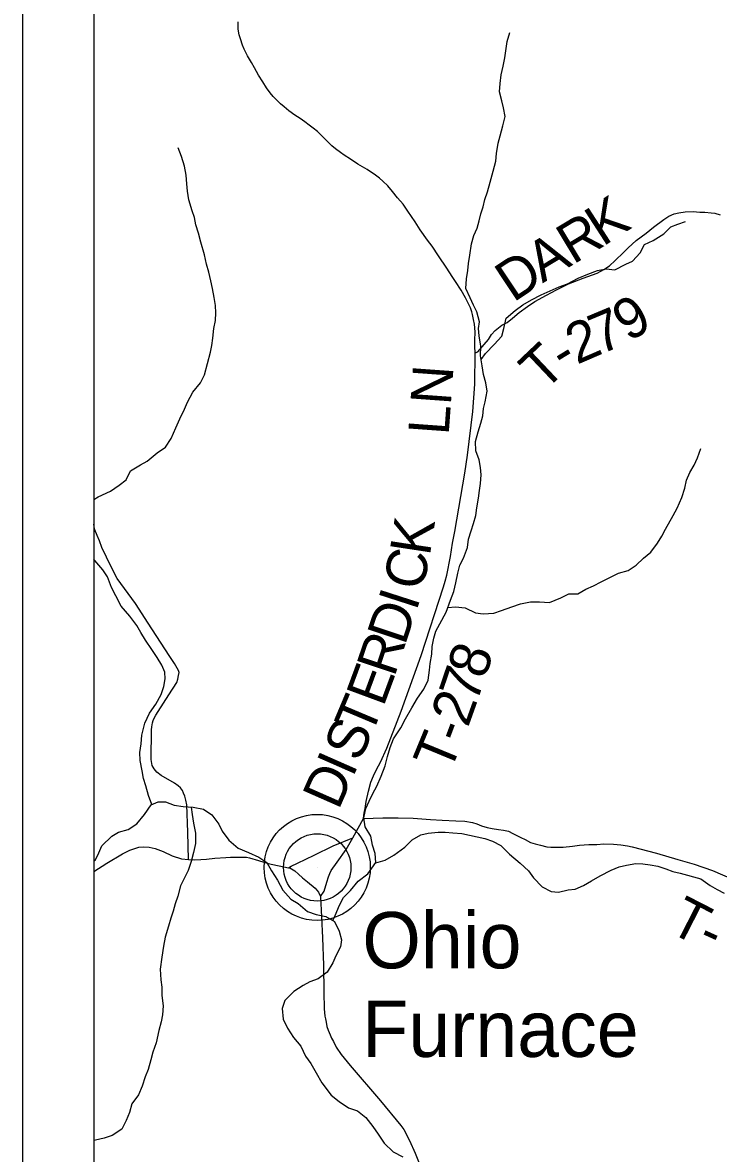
# Model space of a CAD drawing. Extents: x 0 to 34, y 0 to 22.
# Drawn here: x 2 to 2.975, y 14.962 to 16.547 of the extents above; entities that cross this region are included whole.
import ezdxf

# ---------------------------------------------------------------- set-up
doc = ezdxf.new("R2010")
doc.units = 0
for name, color, linetype in [('GM_X_County_Road', 7, 'Continuous'), ('GM_X_County_Text', 7, 'Continuous'), ('GM_X_Minor_River', 7, 'Continuous'), ('GM_X_Township_Road', 7, 'Continuous'), ('GM_X_Township_Road_Text', 7, 'Continuous'), ('GM_X_Unincorporated', 7, 'Continuous'), ('GM_X_Unincorporated_Location', 7, 'Continuous'), ('GM_X_Unincorporated_Text', 7, 'Continuous'), ('SH_Cut_Line', 7, 'Continuous'), ('SH_Data', 7, 'Continuous')]:
    doc.layers.add(name, color=color, linetype=linetype)

msp = doc.modelspace()

# ---------------------------------------------------------------- linework, layer by layer
at = {"layer": 'GM_X_County_Road'}
msp.add_lwpolyline([(2.1, 15.3571), (2.1182, 15.3686), (2.14, 15.3816), (2.1501, 15.387), (2.1572, 15.3894), (2.1627, 15.3911), (2.1701, 15.3915), (2.1772, 15.3913), (2.1859, 15.389), (2.1972, 15.3848), (2.2097, 15.3791), (2.2225, 15.3749), (2.2326, 15.3739), (2.2411, 15.3731), (2.2498, 15.3737), (2.2577, 15.3745), (2.2696, 15.3757), (2.2847, 15.3767), (2.2914, 15.3771), (2.2979, 15.3769), (2.3066, 15.3773), (2.3136, 15.3773), (2.3181, 15.3761), (2.3308, 15.3725), (2.3444, 15.3682), (2.3725, 15.3622), (2.3745, 15.3619), (2.3814, 15.3577), (2.3868, 15.3531), (2.3925, 15.3482), (2.3992, 15.3425), (2.4099, 15.3334), (2.4145, 15.3278), (2.4177, 15.3219), (2.4204, 15.2641), (2.4218, 15.2257), (2.4224, 15.1879), (2.4228, 15.1645), (2.4236, 15.1542), (2.4244, 15.1503), (2.4254, 15.1459), (2.4266, 15.1398), (2.4283, 15.1345), (2.4309, 15.1281), (2.4329, 15.1232), (2.4357, 15.1184), (2.4396, 15.1107), (2.4463, 15.1004), (2.459, 15.0848), (2.5018, 15.0353), (2.5299, 15.0009), (2.5342, 14.9951), (2.5425, 14.9799), (2.5502, 14.9621), (2.5617, 14.9332)], dxfattribs=at)
at = {"layer": 'GM_X_Minor_River'}
for points in [[(2.6761, 16.498), (2.6773, 16.5075), (2.6793, 16.5207), (2.6828, 16.5332)], [(2.4347, 15.2883), (2.438, 15.2952), (2.4442, 15.3096), (2.4499, 15.3205), (2.4594, 15.3303), (2.4705, 15.3436), (2.4838, 15.3537), (2.4952, 15.3696), (2.4942, 15.3821), (2.4905, 15.3939), (2.4879, 15.4064), (2.48, 15.4197), (2.4782, 15.4323), (2.4813, 15.4451), (2.4859, 15.4554), (2.4909, 15.4663), (2.4963, 15.4765), (2.5024, 15.4905), (2.5082, 15.5049), (2.5113, 15.5182), (2.5151, 15.5307), (2.5197, 15.5428), (2.53, 15.5583), (2.5369, 15.5711), (2.5457, 15.5866), (2.5537, 15.6002), (2.5625, 15.6127), (2.5686, 15.6252), (2.5702, 15.6392), (2.5711, 15.6487), (2.5734, 15.6619), (2.5742, 15.6725), (2.5762, 15.6843), (2.5793, 15.6941), (2.585, 15.7043), (2.5938, 15.7206), (2.5996, 15.7376), (2.6042, 15.7497), (2.6073, 15.7618), (2.61, 15.7751), (2.6127, 15.7865), (2.6181, 15.7963), (2.6235, 15.8114), (2.6251, 15.8228), (2.6285, 15.8345), (2.632, 15.8448), (2.6351, 15.8561), (2.6367, 15.8667), (2.639, 15.8804), (2.6402, 15.891), (2.6418, 15.9012), (2.6426, 15.913), (2.6416, 15.9236), (2.6397, 15.9342), (2.6353, 15.9468), (2.6346, 15.9597), (2.6385, 15.9733), (2.6423, 15.9858), (2.645, 15.996), (2.6462, 16.0062), (2.6482, 16.0157), (2.6513, 16.0305), (2.6495, 16.0419), (2.6458, 16.0537), (2.644, 16.0658), (2.6418, 16.0802), (2.6422, 16.0935), (2.6401, 16.1079), (2.639, 16.1182), (2.6402, 16.1276), (2.6365, 16.1417), (2.632, 16.1512), (2.6271, 16.1615), (2.6212, 16.1744), (2.622, 16.1881), (2.624, 16.1994), (2.6252, 16.2093), (2.6268, 16.221), (2.6291, 16.2369), (2.6326, 16.2487), (2.6372, 16.2589), (2.6399, 16.2691), (2.6422, 16.279), (2.6457, 16.2888), (2.648, 16.299), (2.6515, 16.31), (2.6554, 16.3233), (2.6596, 16.3388), (2.6631, 16.3528), (2.6643, 16.3638), (2.6667, 16.3782), (2.6694, 16.3884), (2.6733, 16.4024), (2.6764, 16.4153), (2.6742, 16.4278), (2.6716, 16.4377), (2.6683, 16.4499), (2.6695, 16.4616), (2.6707, 16.4741), (2.6734, 16.4862), (2.6761, 16.498)], [(2.1, 15.8784), (2.1058, 15.8821), (2.1233, 15.8903), (2.1351, 15.8986), (2.1453, 15.9061), (2.1511, 15.9186), (2.1651, 15.9272), (2.1746, 15.9321), (2.1887, 15.9441), (2.2004, 15.9517), (2.2081, 15.9641), (2.2146, 15.9789), (2.2203, 15.9917), (2.2269, 16.0054), (2.2311, 16.0152), (2.2387, 16.0288), (2.2494, 16.042), (2.2551, 16.0534), (2.2633, 16.0852), (2.2652, 16.0946), (2.2668, 16.1049), (2.268, 16.1181), (2.2704, 16.1295), (2.2708, 16.1401), (2.2705, 16.1504), (2.2687, 16.1617), (2.2661, 16.1743), (2.2639, 16.1853), (2.2609, 16.1971), (2.2576, 16.2085), (2.255, 16.2214), (2.2499, 16.2392), (2.2465, 16.2518), (2.2428, 16.2636), (2.241, 16.2738), (2.2376, 16.2833), (2.2328, 16.2985), (2.231, 16.311), (2.2303, 16.3209), (2.2293, 16.3334), (2.2271, 16.346), (2.2226, 16.3593), (2.2181, 16.3718)], [(2.6426, 16.0748), (2.649, 16.0832), (2.6608, 16.096), (2.6718, 16.1074), (2.6745, 16.1183), (2.678, 16.1327), (2.6906, 16.1437), (2.7012, 16.1516), (2.7133, 16.1583), (2.727, 16.1654), (2.752, 16.1767), (2.7638, 16.1811), (2.7786, 16.189), (2.7922, 16.1946), (2.8059, 16.1998), (2.818, 16.202), (2.8301, 16.2005), (2.8453, 16.2083), (2.8547, 16.2128), (2.8654, 16.2245), (2.8715, 16.2359), (2.884, 16.2415), (2.8988, 16.2509), (2.9087, 16.2607), (2.9182, 16.2644), (2.9292, 16.2681)], [(2.596, 15.727), (2.6067, 15.7281), (2.6203, 15.7265), (2.635, 15.7196), (2.6456, 15.7184), (2.6607, 15.7194), (2.671, 15.7231), (2.6857, 15.728), (2.6979, 15.7321), (2.7119, 15.735), (2.7244, 15.735), (2.7387, 15.7341), (2.7543, 15.7405), (2.7656, 15.7461), (2.7781, 15.7464), (2.7895, 15.7528), (2.8001, 15.7573), (2.8108, 15.7629), (2.8221, 15.7689), (2.8354, 15.7753), (2.849, 15.779), (2.8601, 15.7865), (2.8703, 15.7963), (2.8806, 15.8046), (2.8901, 15.8174), (2.8962, 15.8272), (2.9012, 15.8371), (2.9119, 15.856), (2.9176, 15.8662), (2.9242, 15.8813), (2.928, 15.8942), (2.9307, 15.9055), (2.9354, 15.9165), (2.9411, 15.9267), (2.9461, 15.9369), (2.9507, 15.9502)], [(2.1811, 15.4507), (2.1763, 15.4637), (2.1729, 15.477), (2.1696, 15.4876), (2.1674, 15.4979), (2.1648, 15.5127), (2.1641, 15.5237), (2.1661, 15.5362), (2.1673, 15.5479), (2.1712, 15.565), (2.1777, 15.579), (2.1869, 15.5918), (2.1941, 15.605), (2.198, 15.6164), (2.1996, 15.627), (2.1993, 15.6365), (2.1952, 15.6464), (2.1888, 15.657), (2.1813, 15.6681), (2.1723, 15.6814), (2.1659, 15.6921), (2.1603, 15.7019), (2.1502, 15.7149), (2.1382, 15.729), (2.1307, 15.7435), (2.1244, 15.7553), (2.1188, 15.7701), (2.1124, 15.78), (2.1011, 15.793), (2.1, 15.7948)], [(2.1, 15.3719), (2.102, 15.3735), (2.1069, 15.3833), (2.1108, 15.3931), (2.1249, 15.4067), (2.1343, 15.4119), (2.148, 15.416), (2.1601, 15.4239), (2.1708, 15.4371), (2.1803, 15.4504), (2.1898, 15.4545), (2.2004, 15.4548), (2.2125, 15.4502), (2.2249, 15.4482), (2.2389, 15.447), (2.2537, 15.4442), (2.2653, 15.4362), (2.2751, 15.4232), (2.2799, 15.4137), (2.2889, 15.4008)], [(2.2361, 15.4472), (2.2377, 15.4367), (2.2396, 15.4246), (2.2421, 15.4109), (2.2424, 15.3961), (2.2397, 15.3836), (2.2362, 15.3708), (2.232, 15.3583), (2.227, 15.3481), (2.2212, 15.3371), (2.2174, 15.3223), (2.2139, 15.3117), (2.2112, 15.3015), (2.2077, 15.2917), (2.2046, 15.2803), (2.2, 15.2651), (2.1976, 15.2523), (2.1953, 15.2367), (2.1929, 15.2201), (2.1936, 15.2053), (2.195, 15.195), (2.1953, 15.1833), (2.1971, 15.1684), (2.1959, 15.1559), (2.194, 15.1461), (2.1909, 15.134), (2.187, 15.1169), (2.1827, 15.1037), (2.1797, 15.0931), (2.1758, 15.0794), (2.1716, 15.0692), (2.1677, 15.056), (2.1623, 15.0439), (2.1532, 15.0314), (2.1497, 15.0189), (2.1451, 15.0079), (2.139, 14.9958), (2.1253, 14.9868), (2.1143, 14.9831), (2.1022, 14.9801), (2.1, 14.98)], [(2.4949, 15.3691), (2.5081, 15.3729), (2.5202, 15.3797), (2.5358, 15.391), (2.5461, 15.4015), (2.5582, 15.4083), (2.5685, 15.4109), (2.5825, 15.4119), (2.5923, 15.4119), (2.6029, 15.411), (2.6157, 15.4102), (2.6369, 15.4055), (2.6478, 15.4032), (2.6584, 15.3997), (2.6701, 15.3936), (2.6825, 15.3813), (2.6975, 15.3687), (2.7092, 15.358), (2.7159, 15.3481), (2.7283, 15.3356), (2.7408, 15.3287), (2.751, 15.3282), (2.7646, 15.3312), (2.7744, 15.3322), (2.7862, 15.3375), (2.7972, 15.3439), (2.8094, 15.351), (2.8249, 15.3589), (2.8363, 15.3633), (2.8465, 15.3659), (2.8594, 15.3681), (2.8692, 15.3677), (2.8798, 15.3665), (2.8904, 15.3645), (2.9017, 15.3607), (2.9115, 15.3568), (2.9217, 15.3545), (2.9504, 15.3467), (2.9636, 15.3375), (2.9737, 15.3318), (2.9835, 15.3268)], [(2.2889, 15.4008), (2.3021, 15.3897), (2.3168, 15.3835), (2.3311, 15.377), (2.3424, 15.3694), (2.3488, 15.3579), (2.3574, 15.3446), (2.3649, 15.3309), (2.3758, 15.318), (2.386, 15.3122), (2.3991, 15.3007), (2.4116, 15.2965), (2.4248, 15.2938), (2.4372, 15.2869), (2.4436, 15.2735), (2.4469, 15.2614), (2.4457, 15.2515), (2.4392, 15.2387), (2.4346, 15.2288), (2.427, 15.216), (2.4144, 15.2066), (2.4027, 15.2021), (2.3932, 15.1972), (2.3803, 15.1886), (2.3674, 15.1762), (2.3639, 15.1648), (2.3653, 15.15), (2.3713, 15.1371), (2.3799, 15.1241), (2.39, 15.1123), (2.3967, 15.0982), (2.4039, 15.0876), (2.4114, 15.0746), (2.4192, 15.0605), (2.4323, 15.0434), (2.4436, 15.0346), (2.4568, 15.0258), (2.4693, 15.0215), (2.4813, 15.012), (2.4907, 14.9994), (2.4982, 14.9888), (2.5068, 14.9762), (2.5192, 14.964), (2.5328, 14.9571)]]:
    msp.add_lwpolyline(points, dxfattribs=at)
at = {"layer": 'GM_X_Township_Road'}
for points in [[(2.3107, 16.5099), (2.3081, 16.5157), (2.3053, 16.5245), (2.3034, 16.53), (2.302, 16.5378), (2.3019, 16.5481)], [(2.4177, 15.3219), (2.4228, 15.3296), (2.4266, 15.3421), (2.4287, 15.3496), (2.4307, 15.3543), (2.4327, 15.3583), (2.441, 15.3702), (2.4535, 15.388), (2.463, 15.4044), (2.4776, 15.4315), (2.4784, 15.4359), (2.4793, 15.4409), (2.4801, 15.4453), (2.4816, 15.4549), (2.4849, 15.4698), (2.4883, 15.482), (2.492, 15.4912), (2.4962, 15.4998), (2.5017, 15.5104), (2.5105, 15.5297), (2.5304, 15.5816), (2.5584, 15.6597), (2.59, 15.7562), (2.5925, 15.7642), (2.5944, 15.7724), (2.5997, 15.7985), (2.6026, 15.8172), (2.6057, 15.8339), (2.62, 15.9154), (2.6237, 15.9407), (2.6309, 16.0021), (2.6338, 16.0404), (2.6343, 16.084), (2.6338, 16.093), (2.634, 16.1015), (2.6341, 16.1137), (2.6334, 16.1244), (2.6322, 16.1309), (2.6305, 16.1377), (2.6296, 16.1415), (2.6277, 16.1472), (2.6256, 16.152), (2.6208, 16.1611), (2.6149, 16.172), (2.6069, 16.184), (2.6022, 16.1914), (2.5947, 16.2027), (2.5827, 16.2204), (2.574, 16.2339), (2.5677, 16.2423), (2.5574, 16.2565), (2.55, 16.268), (2.5401, 16.2826), (2.5332, 16.2925), (2.5256, 16.3017), (2.5184, 16.3106), (2.5117, 16.3182), (2.5048, 16.3249), (2.5001, 16.3291), (2.4944, 16.3335), (2.4829, 16.3411), (2.47, 16.3489), (2.4597, 16.3556), (2.4506, 16.3615), (2.4454, 16.3651), (2.4384, 16.37), (2.4336, 16.3746), (2.4287, 16.379), (2.4241, 16.3837), (2.4195, 16.3885), (2.4131, 16.3944), (2.4073, 16.399), (2.4018, 16.4032), (2.3954, 16.4079), (2.3891, 16.4127), (2.3816, 16.4176), (2.3731, 16.4234), (2.3664, 16.4291), (2.3613, 16.4335), (2.3561, 16.4386), (2.3514, 16.4434), (2.3468, 16.4489), (2.342, 16.4557), (2.3365, 16.4643), (2.3308, 16.4736), (2.3251, 16.4839), (2.3207, 16.4912), (2.315, 16.5005), (2.3119, 16.507), (2.3107, 16.5099)], [(2.6343, 16.084), (2.6382, 16.0856), (2.6528, 16.103), (2.6574, 16.1097), (2.6625, 16.1155), (2.6719, 16.1229), (2.679, 16.1268), (2.6868, 16.1329), (2.696, 16.1407), (2.7075, 16.1492), (2.718, 16.1562), (2.7345, 16.1652), (2.7483, 16.1723), (2.7653, 16.1809), (2.7856, 16.189), (2.8055, 16.1961), (2.8147, 16.2008), (2.8224, 16.206), (2.8304, 16.2135), (2.8423, 16.225), (2.8486, 16.2313), (2.8599, 16.2416), (2.8742, 16.2521), (2.8842, 16.2604), (2.8989, 16.2713), (2.906, 16.2757), (2.9133, 16.2789), (2.92, 16.2803), (2.9288, 16.2818), (2.9401, 16.2822), (2.9491, 16.2816), (2.9564, 16.2814), (2.965, 16.2807), (2.9703, 16.2799), (2.9776, 16.2776)], [(2.2326, 15.3739), (2.2318, 15.4123), (2.23, 15.4505), (2.2287, 15.4572), (2.2273, 15.4628), (2.2255, 15.4669), (2.2239, 15.4705), (2.2213, 15.4741), (2.218, 15.4772), (2.2128, 15.4808), (2.1944, 15.4915), (2.1881, 15.4964), (2.1845, 15.501), (2.1818, 15.5055), (2.1802, 15.5142), (2.1806, 15.5554), (2.1812, 15.56), (2.1821, 15.5655), (2.1831, 15.5689), (2.1845, 15.5718), (2.1865, 15.5762), (2.1899, 15.5813), (2.205, 15.6046), (2.2162, 15.6221), (2.2176, 15.6268), (2.2186, 15.632), (2.2192, 15.6358), (2.2186, 15.6387), (2.213, 15.6488), (2.2053, 15.6597), (2.1758, 15.7052), (2.158, 15.7327), (2.1327, 15.768), (2.1263, 15.7796), (2.1176, 15.7976), (2.1111, 15.8111), (2.1077, 15.8208), (2.1044, 15.8279), (2.101, 15.8362), (2.1002, 15.8402), (2.1, 15.8438), (2.1, 15.8439)], [(2.4776, 15.4315), (2.5049, 15.4321), (2.5263, 15.4321), (2.5473, 15.4319), (2.5716, 15.4301), (2.5879, 15.4289), (2.607, 15.4278), (2.6199, 15.4276), (2.6304, 15.4256), (2.6367, 15.4236), (2.6433, 15.4208), (2.651, 15.4185), (2.6583, 15.4171), (2.667, 15.4159), (2.6741, 15.4147), (2.6811, 15.4133), (2.6872, 15.4103), (2.6925, 15.4076), (2.6985, 15.4048), (2.7044, 15.402), (2.7121, 15.3977), (2.7185, 15.3959), (2.726, 15.3937), (2.7349, 15.3917), (2.7404, 15.3911), (2.7476, 15.3909), (2.7579, 15.3909), (2.7709, 15.3927), (2.7806, 15.3941), (2.7937, 15.3947), (2.8048, 15.3947), (2.8145, 15.3957), (2.8283, 15.3955), (2.8386, 15.3943), (2.8477, 15.3931), (2.8546, 15.3915), (2.8883, 15.3828), (2.9182, 15.3737), (2.9411, 15.3672), (2.9668, 15.3585), (2.9981, 15.3448)], [(2.3725, 15.3622), (2.3765, 15.3644), (2.3854, 15.3686), (2.4087, 15.3801), (2.4355, 15.3931), (2.463, 15.4044)]]:
    msp.add_lwpolyline(points, dxfattribs=at)
at = {"layer": 'GM_X_Unincorporated'}
msp.add_lwpolyline([(2.2853, 20.9), (2.1, 20.9), (2.1, 14.1), (2.8399, 14.1), (2.9778, 14.1609), (3.8099, 14.5285), (4.2904, 14.7408), (4.3998, 14.7897), (4.802, 14.9692), (4.4847, 15.685), (4.2937, 16.1161), (4.0882, 16.6114), (3.972, 16.8916), (3.7367, 17.4136), (3.709, 17.484), (3.4011, 18.2653), (3.1249, 18.9173), (3.0781, 19.0279), (2.9956, 19.2227), (2.9553, 19.318), (2.7473, 19.8121), (2.418, 20.5866)], close=True, dxfattribs=at)
for radius in [0.0744, 0.0472]:
    msp.add_circle((2.4129, 15.3627), radius, dxfattribs=at)
at = {"layer": 'GM_X_Unincorporated_Location'}
msp.add_line((2.4129, 15.3627), (2.4129, 15.3627), dxfattribs=at)
at = {"layer": 'SH_Cut_Line'}
msp.add_lwpolyline([(2.1, 20.9), (2.1, 14.1), (2.8399, 14.1), (2.9778, 14.1609), (3.8099, 14.5285), (4.2904, 14.7408), (4.3998, 14.7897), (4.802, 14.9692), (4.4847, 15.685), (4.2937, 16.1161), (4.0882, 16.6114)], dxfattribs=at)
at = {"layer": 'SH_Data'}
for p, q in [((2, 21), (2, 14)), ((2.1, 20.9), (2.1, 14.1))]:
    msp.add_line(p, q, dxfattribs=at)

# ---------------------------------------------------------------- texts
at = {"layer": 'GM_X_County_Text'}
msp.add_text('SCIOTO COUNTY', height=0.189394, rotation=23.8999, dxfattribs=at).set_placement((2.8904, 14.2774))
at = {"layer": 'GM_X_Township_Road_Text'}
for s, height, rotation, p in [('K', 0.0568, 32.8784, (2.8131, 16.2325)), ('R', 0.0568, 31.1063, (2.7715, 16.2074)), ('A', 0.0568, 31.2377, (2.7288, 16.1815)), ('D', 0.0568, 33.586, (2.6876, 16.1541)), ('9', 0.0568, 31.1942, (2.8494, 16.0987)), ('7', 0.0568, 22.6755, (2.8089, 16.0811)), ('2', 0.0568, 23.3985, (2.7769, 16.0673)), ('T', 0.0568, 43.4604, (2.7305, 16.0288)), ('-', 0.0568, 31.3674, (2.7589, 16.0561)), ('LN', 0.05682, 85.878, (2.5971, 15.9678)), ('K', 0.0568, 81.323, (2.5707, 15.7983)), ('C', 0.0568, 78.2795, (2.5606, 15.7493)), ('I', 0.0568, 72.1053, (2.5517, 15.7207)), ('D', 0.0568, 71.5771, (2.5357, 15.6727)), ('R', 0.0568, 71.4558, (2.5209, 15.6283)), ('8', 0.0568, 71.4122, (2.6475, 15.625)), ('E', 0.0568, 69.679, (2.5055, 15.5866)), ('7', 0.0568, 71.2011, (2.6362, 15.5916)), ('T', 0.0568, 67.1707, (2.488, 15.5449)), ('2', 0.0568, 70.3461, (2.6241, 15.5578)), ('S', 0.0568, 66.2519, (2.4721, 15.5089)), ('T', 0.0568, 67.5659, (2.5986, 15.4938)), ('-', 0.0568, 69.4644, (2.6156, 15.535)), ('I', 0.0568, 66.2428, (2.4627, 15.4876)), ('D', 0.0568, 66.2446, (2.4426, 15.4418)), ('T', 0.0568, 332.8753, (2.9033, 15.2736)), ('-', 0.0568, 335.4889, (2.9437, 15.253))]:
    msp.add_text(s, height=height, rotation=rotation, dxfattribs=at).set_placement(p)
at = {"layer": 'GM_X_Unincorporated_Text'}
for s, p in [('Ohio', (2.4761, 15.2212)), ('Furnace', (2.4761, 15.097))]:
    msp.add_text(s, height=0.07898, rotation=0, dxfattribs=at).set_placement(p)

doc.saveas('drawing.dxf')
